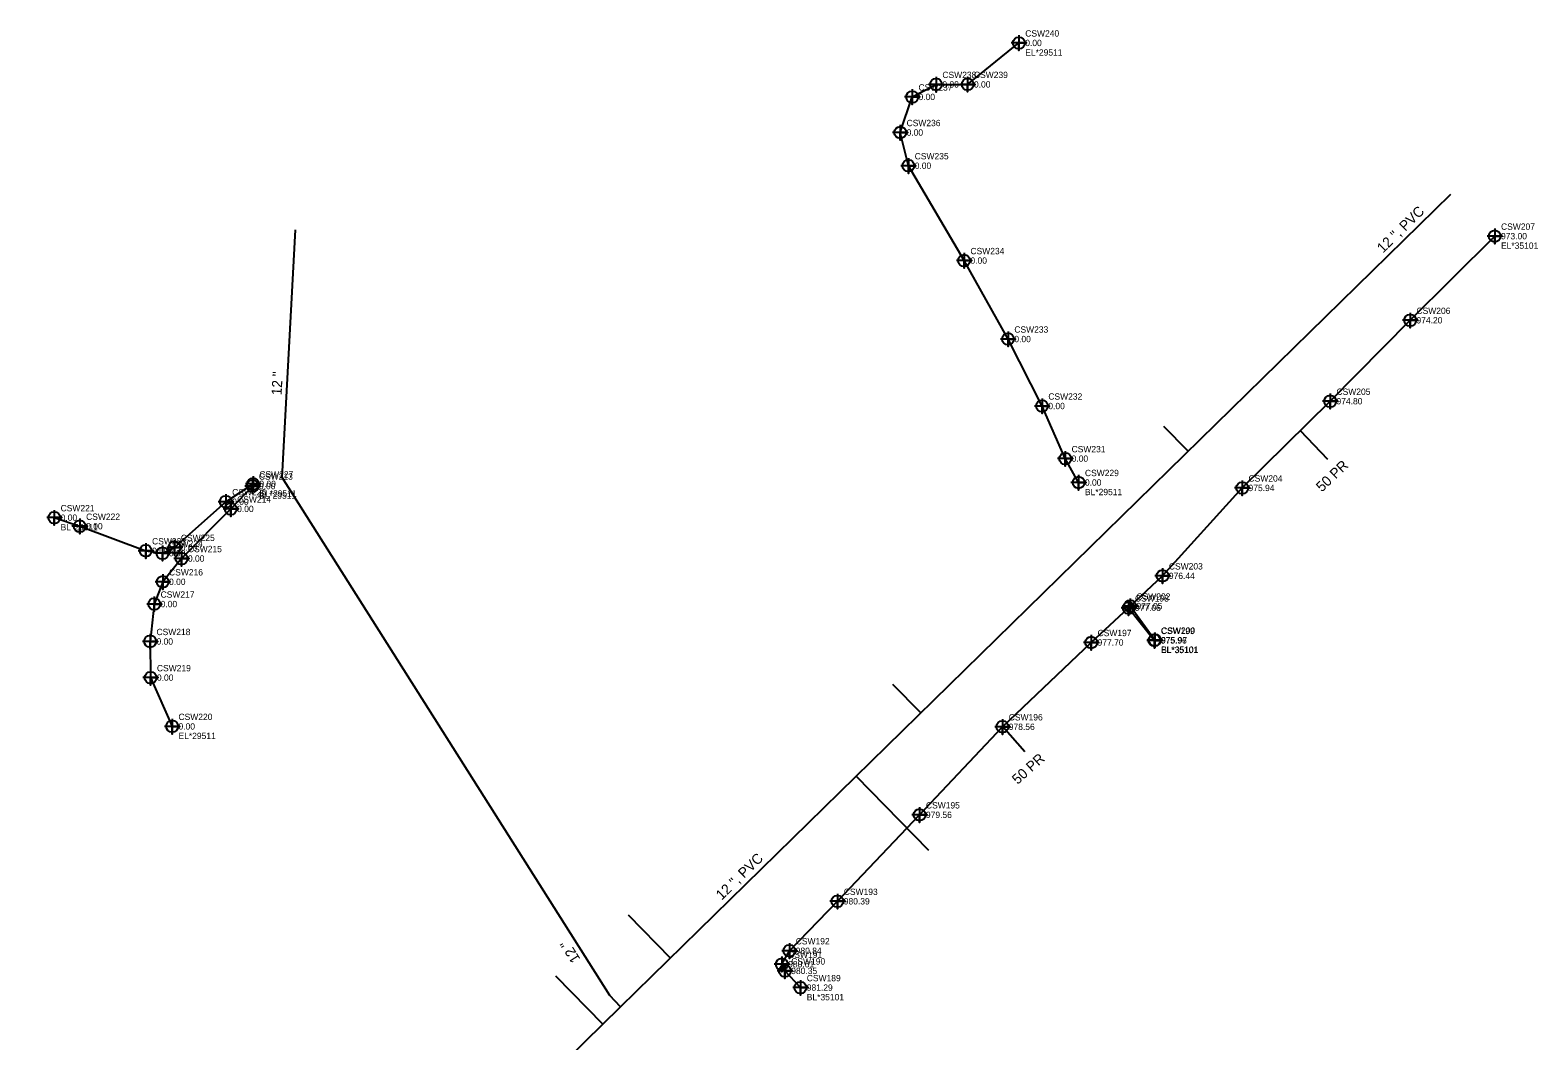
# Model space of a CAD drawing. Extents: x 1182504 to 1186036, y 573002 to 575111.
# Drawn here: x 1184871 to 1185466, y 574713 to 575111 of the extents above; entities that cross this region are included whole.
import ezdxf

# ---------------------------------------------------------------- set-up
doc = ezdxf.new("R2010")
doc.units = 0
for name, color, linetype in [('Exist Utilities Power UG Cable SUE LOS B', 7, 'Continuous'), ('Exist Utilities Power UG Cable SUE LOS B Cogo Comment', 7, 'Continuous'), ('Exist Utilities Power UG Cable SUE LOS B Cogo Elevation', 7, 'Continuous'), ('Exist Utilities Power UG Cable SUE LOS B Cogo Number', 7, 'Continuous'), ('Exist Utilities Power UG Cable SUE LOS B Cogo Point CELL', 7, 'Continuous'), ('Exist Utilities Telephone UG Cable SUE LOS C', 7, 'Continuous'), ('Exist Utilities Telephone UG Cable SUE LOS C Cogo Comment', 7, 'Continuous'), ('Exist Utilities Telephone UG Cable SUE LOS C Cogo Elevation', 7, 'Continuous'), ('Exist Utilities Telephone UG Cable SUE LOS C Cogo Number', 7, 'Continuous'), ('Exist Utilities Telephone UG Cable SUE LOS C Cogo Point CELL', 7, 'Continuous'), ('Exist Utilities Telephone UG Cable SUE LOS C Leader', 7, 'Continuous'), ('Exist Utilities Telephone UG Cable SUE LOS C Text', 7, 'Continuous'), ('Exist Utilities Water UG Line SUE LOS C', 7, 'Continuous'), ('Exist Utilities Water UG Line SUE LOS C Text', 7, 'Continuous')]:
    doc.layers.add(name, color=color, linetype=linetype)

msp = doc.modelspace()

# ---------------------------------------------------------------- linework, layer by layer
at = {"layer": 'Exist Utilities Power UG Cable SUE LOS B'}
for points in [[(1185284.48, 574933.16), (1185279.22, 574942.56), (1185270.05, 574963.3), (1185256.65, 574989.7), (1185239.34, 575020.62), (1185217.36, 575058), (1185214.16, 575071.09), (1185218.87, 575085.11), (1185228.28, 575090.05), (1185240.72, 575090.06), (1185260.95, 575106.39)], [(1184880.64, 574919.3), (1184890.69, 574915.92), (1184916.69, 574906.24), (1184923.29, 574905.29), (1184928.03, 574907.57), (1184948.27, 574925.58), (1184958.99, 574932.62)], [(1184958.81, 574931.76), (1184950.23, 574922.75), (1184930.83, 574903.19), (1184923.38, 574894.02), (1184920.06, 574885.26), (1184918.44, 574870.51), (1184918.6, 574856.25), (1184927.11, 574837.04)]]:
    msp.add_lwpolyline(points, dxfattribs=at)
at = {"layer": 'Exist Utilities Power UG Cable SUE LOS B Cogo Point CELL'}
for points in [[(1185260.95, 575109.39), (1185260.95, 575103.39), (1185260.95, 575106.39), (1185263.95, 575106.39), (1185257.95, 575106.39)], [(1185228.28, 575093.05), (1185228.28, 575087.05), (1185228.28, 575090.05), (1185231.28, 575090.05), (1185225.28, 575090.05)], [(1185240.72, 575093.06), (1185240.72, 575087.06), (1185240.72, 575090.06), (1185243.72, 575090.06), (1185237.72, 575090.06)], [(1185218.87, 575088.11), (1185218.87, 575082.11), (1185218.87, 575085.11), (1185221.87, 575085.11), (1185215.87, 575085.11)], [(1185214.16, 575074.09), (1185214.16, 575068.09), (1185214.16, 575071.09), (1185217.16, 575071.09), (1185211.16, 575071.09)], [(1185217.36, 575061), (1185217.36, 575055), (1185217.36, 575058), (1185220.36, 575058), (1185214.36, 575058)], [(1185239.34, 575023.62), (1185239.34, 575017.62), (1185239.34, 575020.62), (1185242.34, 575020.62), (1185236.34, 575020.62)], [(1185256.65, 574992.7), (1185256.65, 574986.7), (1185256.65, 574989.7), (1185259.65, 574989.7), (1185253.65, 574989.7)], [(1185270.05, 574966.3), (1185270.05, 574960.3), (1185270.05, 574963.3), (1185273.05, 574963.3), (1185267.05, 574963.3)], [(1185279.22, 574945.56), (1185279.22, 574939.56), (1185279.22, 574942.56), (1185282.22, 574942.56), (1185276.22, 574942.56)], [(1184958.81, 574934.76), (1184958.81, 574928.76), (1184958.81, 574931.76), (1184961.81, 574931.76), (1184955.81, 574931.76)], [(1184958.99, 574935.62), (1184958.99, 574929.62), (1184958.99, 574932.62), (1184961.99, 574932.62), (1184955.99, 574932.62)], [(1185284.48, 574936.16), (1185284.48, 574930.16), (1185284.48, 574933.16), (1185287.48, 574933.16), (1185281.48, 574933.16)], [(1184948.27, 574928.58), (1184948.27, 574922.58), (1184948.27, 574925.58), (1184951.27, 574925.58), (1184945.27, 574925.58)], [(1184950.23, 574925.75), (1184950.23, 574919.75), (1184950.23, 574922.75), (1184953.23, 574922.75), (1184947.23, 574922.75)], [(1184880.64, 574922.3), (1184880.64, 574916.3), (1184880.64, 574919.3), (1184883.64, 574919.3), (1184877.64, 574919.3)], [(1184890.69, 574918.92), (1184890.69, 574912.92), (1184890.69, 574915.92), (1184893.69, 574915.92), (1184887.69, 574915.92)], [(1184916.69, 574909.24), (1184916.69, 574903.24), (1184916.69, 574906.24), (1184919.69, 574906.24), (1184913.69, 574906.24)], [(1184923.29, 574908.29), (1184923.29, 574902.29), (1184923.29, 574905.29), (1184926.29, 574905.29), (1184920.29, 574905.29)], [(1184928.03, 574910.57), (1184928.03, 574904.57), (1184928.03, 574907.57), (1184931.03, 574907.57), (1184925.03, 574907.57)], [(1184930.83, 574906.19), (1184930.83, 574900.19), (1184930.83, 574903.19), (1184933.83, 574903.19), (1184927.83, 574903.19)], [(1184923.38, 574897.02), (1184923.38, 574891.02), (1184923.38, 574894.02), (1184926.38, 574894.02), (1184920.38, 574894.02)], [(1184920.06, 574888.26), (1184920.06, 574882.26), (1184920.06, 574885.26), (1184923.06, 574885.26), (1184917.06, 574885.26)], [(1184918.44, 574873.51), (1184918.44, 574867.51), (1184918.44, 574870.51), (1184921.44, 574870.51), (1184915.44, 574870.51)], [(1184918.6, 574859.25), (1184918.6, 574853.25), (1184918.6, 574856.25), (1184921.6, 574856.25), (1184915.6, 574856.25)], [(1184927.11, 574840.04), (1184927.11, 574834.04), (1184927.11, 574837.04), (1184930.11, 574837.04), (1184924.11, 574837.04)]]:
    msp.add_lwpolyline(points, dxfattribs=at)
for centre in [(1185260.95, 575106.39), (1185228.28, 575090.05), (1185240.72, 575090.06), (1185218.87, 575085.11), (1185214.16, 575071.09), (1185217.36, 575058), (1185239.34, 575020.62), (1185256.65, 574989.7), (1185270.05, 574963.3), (1185279.22, 574942.56), (1184958.81, 574931.76), (1184958.99, 574932.62), (1185284.48, 574933.16), (1184948.27, 574925.58), (1184950.23, 574922.75), (1184880.64, 574919.3), (1184890.69, 574915.92), (1184916.69, 574906.24), (1184923.29, 574905.29), (1184928.03, 574907.57), (1184930.83, 574903.19), (1184923.38, 574894.02), (1184920.06, 574885.26), (1184918.44, 574870.51), (1184918.6, 574856.25), (1184927.11, 574837.04)]:
    msp.add_circle(centre, 2.34, dxfattribs=at)
at = {"layer": 'Exist Utilities Telephone UG Cable SUE LOS C'}
for points in [[(1185314.54, 574871.05), (1185304.79, 574884.46), (1185317.57, 574896.37), (1185348.98, 574931.01), (1185383.66, 574965.19), (1185415.19, 574997.09), (1185448.52, 575030.25)], [(1185174.81, 574734.09), (1185168.69, 574740.67), (1185167.47, 574743.31), (1185170.46, 574748.61), (1185189.4, 574768.11), (1185221.79, 574802.19), (1185254.45, 574836.88), (1185289.46, 574870.1), (1185304.2, 574883.75), (1185314.39, 574870.91)]]:
    msp.add_lwpolyline(points, dxfattribs=at)
at = {"layer": 'Exist Utilities Telephone UG Cable SUE LOS C Cogo Point CELL'}
for points in [[(1185448.52, 575033.25), (1185448.52, 575027.25), (1185448.52, 575030.25), (1185451.52, 575030.25), (1185445.52, 575030.25)], [(1185415.19, 575000.09), (1185415.19, 574994.09), (1185415.19, 574997.09), (1185418.19, 574997.09), (1185412.19, 574997.09)], [(1185383.66, 574968.19), (1185383.66, 574962.19), (1185383.66, 574965.19), (1185386.66, 574965.19), (1185380.66, 574965.19)], [(1185348.98, 574934.01), (1185348.98, 574928.01), (1185348.98, 574931.01), (1185351.98, 574931.01), (1185345.98, 574931.01)], [(1185317.57, 574899.37), (1185317.57, 574893.37), (1185317.57, 574896.37), (1185320.57, 574896.37), (1185314.57, 574896.37)], [(1185304.2, 574886.75), (1185304.2, 574880.75), (1185304.2, 574883.75), (1185307.2, 574883.75), (1185301.2, 574883.75)], [(1185304.79, 574887.46), (1185304.79, 574881.46), (1185304.79, 574884.46), (1185307.79, 574884.46), (1185301.79, 574884.46)], [(1185289.46, 574873.1), (1185289.46, 574867.1), (1185289.46, 574870.1), (1185292.46, 574870.1), (1185286.46, 574870.1)], [(1185314.39, 574873.91), (1185314.39, 574867.91), (1185314.39, 574870.91), (1185317.39, 574870.91), (1185311.39, 574870.91)], [(1185314.54, 574874.05), (1185314.54, 574868.05), (1185314.54, 574871.05), (1185317.54, 574871.05), (1185311.54, 574871.05)], [(1185254.45, 574839.88), (1185254.45, 574833.88), (1185254.45, 574836.88), (1185257.45, 574836.88), (1185251.45, 574836.88)], [(1185221.79, 574805.19), (1185221.79, 574799.19), (1185221.79, 574802.19), (1185224.79, 574802.19), (1185218.79, 574802.19)], [(1185189.4, 574771.11), (1185189.4, 574765.11), (1185189.4, 574768.11), (1185192.4, 574768.11), (1185186.4, 574768.11)], [(1185170.46, 574751.61), (1185170.46, 574745.61), (1185170.46, 574748.61), (1185173.46, 574748.61), (1185167.46, 574748.61)], [(1185167.47, 574746.31), (1185167.47, 574740.31), (1185167.47, 574743.31), (1185170.47, 574743.31), (1185164.47, 574743.31)], [(1185168.69, 574743.67), (1185168.69, 574737.67), (1185168.69, 574740.67), (1185171.69, 574740.67), (1185165.69, 574740.67)], [(1185174.81, 574737.09), (1185174.81, 574731.09), (1185174.81, 574734.09), (1185177.81, 574734.09), (1185171.81, 574734.09)]]:
    msp.add_lwpolyline(points, dxfattribs=at)
for centre in [(1185448.52, 575030.25), (1185415.19, 574997.09), (1185383.66, 574965.19), (1185348.98, 574931.01), (1185317.57, 574896.37), (1185304.2, 574883.75), (1185304.79, 574884.46), (1185289.46, 574870.1), (1185314.39, 574870.91), (1185314.54, 574871.05), (1185254.45, 574836.88), (1185221.79, 574802.19), (1185189.4, 574768.11), (1185170.46, 574748.61), (1185167.47, 574743.31), (1185168.69, 574740.67), (1185174.81, 574734.09)]:
    msp.add_circle(centre, 2.34, dxfattribs=at)
at = {"layer": 'Exist Utilities Telephone UG Cable SUE LOS C Leader'}
for p, q in [((1185371.89, 574953.59), (1185382.61, 574942.36)), ((1185254.57, 574837), (1185263.29, 574827.21))]:
    msp.add_line(p, q, dxfattribs=at)
at = {"layer": 'Exist Utilities Water UG Line SUE LOS C'}
for p, q in [((1185317.95, 574955.36), (1185327.4, 574945.72)), ((1185211.15, 574853.66), (1185222.12, 574842.47)), ((1185225.43, 574788.19), (1185196.82, 574817.43)), ((1185106.93, 574762.71), (1185123.53, 574745.74)), ((1185078.29, 574738.67), (1185096.87, 574719.67))]:
    msp.add_line(p, q, dxfattribs=at)
for points in [[(1184698.37, 574456.58), (1184835.97, 574463.78), (1185103.91, 574726.55), (1185431.28, 575046.78)], [(1185103.91, 574726.55), (1185099.65, 574730.99), (1184970.48, 574935.12), (1184975.79, 575032.78)]]:
    msp.add_lwpolyline(points, dxfattribs=at)

# ---------------------------------------------------------------- texts
at = {"layer": 'Exist Utilities Power UG Cable SUE LOS B Cogo Comment'}
for s, p in [('EL*29511', (1185263.45, 575101.39)), ('BL*29511', (1184961.31, 574926.76)), ('EL*29511', (1184961.49, 574927.62)), ('BL*29511', (1185286.98, 574928.16)), ('BL*29511', (1184883.14, 574914.3)), ('EL*29511', (1184929.61, 574832.04))]:
    msp.add_text(s, height=2.5, dxfattribs=at).set_placement(p)
at = {"layer": 'Exist Utilities Power UG Cable SUE LOS B Cogo Elevation'}
for p in [(1185263.45, 575105.14), (1185221.37, 575083.86), (1185230.78, 575088.8), (1185243.22, 575088.81), (1185216.66, 575069.84), (1185219.86, 575056.75), (1185241.84, 575019.37), (1185259.15, 574988.45), (1185272.55, 574962.05), (1185281.72, 574941.31), (1184961.31, 574930.51), (1184961.49, 574931.37), (1185286.98, 574931.91), (1184950.77, 574924.33), (1184883.14, 574918.05), (1184952.73, 574921.5), (1184893.19, 574914.67), (1184919.19, 574904.99), (1184930.53, 574906.32), (1184925.79, 574904.04), (1184933.33, 574901.94), (1184925.88, 574892.77), (1184922.56, 574884.01), (1184920.94, 574869.26), (1184921.1, 574855), (1184929.61, 574835.79)]:
    msp.add_text('0.00', height=2.5, dxfattribs=at).set_placement(p)
at = {"layer": 'Exist Utilities Power UG Cable SUE LOS B Cogo Number'}
for s, p in [('CSW240', (1185263.45, 575108.89)), ('CSW238', (1185230.78, 575092.55)), ('CSW239', (1185243.22, 575092.56)), ('CSW237', (1185221.37, 575087.61)), ('CSW236', (1185216.66, 575073.59)), ('CSW235', (1185219.86, 575060.5)), ('CSW234', (1185241.84, 575023.12)), ('CSW233', (1185259.15, 574992.2)), ('CSW232', (1185272.55, 574965.8)), ('CSW231', (1185281.72, 574945.06)), ('CSW227', (1184961.49, 574935.12)), ('CSW229', (1185286.98, 574935.66)), ('CSW213', (1184961.31, 574934.26)), ('CSW226', (1184950.77, 574928.08)), ('CSW214', (1184952.73, 574925.25)), ('CSW221', (1184883.14, 574921.8)), ('CSW222', (1184893.19, 574918.42)), ('CSW223', (1184919.19, 574908.74)), ('CSW224', (1184925.79, 574907.79)), ('CSW225', (1184930.53, 574910.07)), ('CSW215', (1184933.33, 574905.69)), ('CSW216', (1184925.88, 574896.52)), ('CSW217', (1184922.56, 574887.76)), ('CSW218', (1184920.94, 574873.01)), ('CSW219', (1184921.1, 574858.75)), ('CSW220', (1184929.61, 574839.54))]:
    msp.add_text(s, height=2.5, dxfattribs=at).set_placement(p)
at = {"layer": 'Exist Utilities Telephone UG Cable SUE LOS C Cogo Comment'}
for s, p in [('EL*35101', (1185451.02, 575025.25)), ('EL*35101', (1185316.89, 574865.91)), ('BL*35101', (1185317.04, 574866.05)), ('BL*35101', (1185177.31, 574729.09))]:
    msp.add_text(s, height=2.5, dxfattribs=at).set_placement(p)
at = {"layer": 'Exist Utilities Telephone UG Cable SUE LOS C Cogo Elevation'}
for s, p in [('973.00', (1185451.02, 575029)), ('974.20', (1185417.69, 574995.84)), ('974.80', (1185386.16, 574963.94)), ('975.94', (1185351.48, 574929.76)), ('976.44', (1185320.07, 574895.12)), ('977.06', (1185306.7, 574882.5)), ('977.05', (1185307.29, 574883.21)), ('975.96', (1185316.89, 574869.66)), ('975.97', (1185317.04, 574869.8)), ('977.70', (1185291.96, 574868.85)), ('978.56', (1185256.95, 574835.63)), ('979.56', (1185224.29, 574800.94)), ('980.39', (1185191.9, 574766.86)), ('980.84', (1185172.96, 574747.36)), ('980.61', (1185169.97, 574742.06)), ('980.35', (1185171.19, 574739.42)), ('981.29', (1185177.31, 574732.84))]:
    msp.add_text(s, height=2.5, dxfattribs=at).set_placement(p)
at = {"layer": 'Exist Utilities Telephone UG Cable SUE LOS C Cogo Number'}
for s, p in [('CSW207', (1185451.02, 575032.75)), ('CSW206', (1185417.69, 574999.59)), ('CSW205', (1185386.16, 574967.69)), ('CSW204', (1185351.48, 574933.51)), ('CSW203', (1185320.07, 574898.87)), ('CSW202', (1185307.29, 574886.96)), ('CSW198', (1185306.7, 574886.25)), ('CSW197', (1185291.96, 574872.6)), ('CSW199', (1185316.89, 574873.41)), ('CSW200', (1185317.04, 574873.55)), ('CSW196', (1185256.95, 574839.38)), ('CSW195', (1185224.29, 574804.69)), ('CSW193', (1185191.9, 574770.61)), ('CSW192', (1185172.96, 574751.11)), ('CSW191', (1185169.97, 574745.81)), ('CSW190', (1185171.19, 574743.17)), ('CSW189', (1185177.31, 574736.59))]:
    msp.add_text(s, height=2.5, dxfattribs=at).set_placement(p)
at = {"layer": 'Exist Utilities Telephone UG Cable SUE LOS C Text'}
for rotation, p in [(43.63759, (1185380.41, 574929.21)), (41.68802, (1185260.41, 574813.94))]:
    msp.add_text('50 PR', height=4, rotation=rotation, dxfattribs=at).set_placement(p)
at = {"layer": 'Exist Utilities Water UG Line SUE LOS C Text'}
for s, rotation, p in [('12 ", PVC', 44.36848, (1185404.47, 575023.36)), ('12 "', 86.88826, (1184970.24, 574967.45)), ('12 ", PVC', 44.36848, (1185143.8, 574768.36)), ('12 "', 122.32313, (1185088.17, 574745.39))]:
    msp.add_text(s, height=4, rotation=rotation, dxfattribs=at).set_placement(p)

doc.saveas('drawing.dxf')
